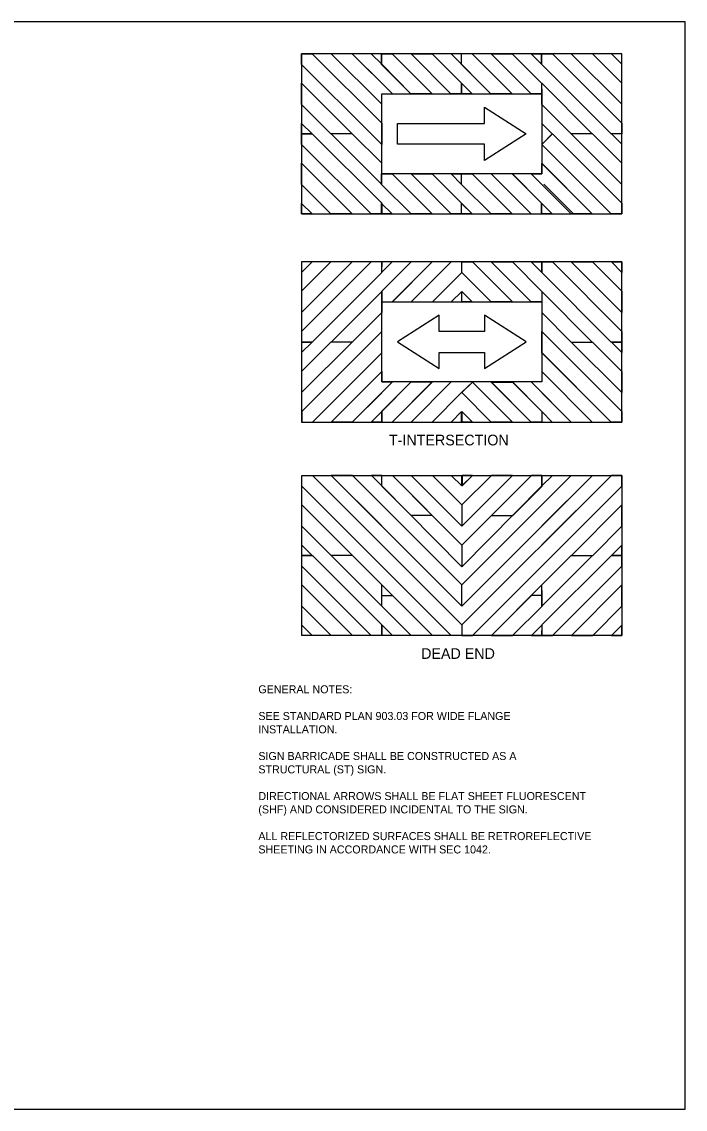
# Model space of a CAD drawing. Extents: x -439.1 to -407.9, y -458.1 to -437.7.
# Drawn here: x -420.29 to -407.86, y -458.05 to -437.68 of the extents above; entities that cross this region are included whole.
import ezdxf

# ---------------------------------------------------------------- set-up
doc = ezdxf.new("R2010")
doc.units = 0
for name, color, linetype in [('Draft_Named_Boundary', 7, 'Continuous'), ('Level 4', 7, 'Continuous'), ('Level 45', 7, 'Continuous')]:
    doc.layers.add(name, color=color, linetype=linetype)

msp = doc.modelspace()

# ---------------------------------------------------------------- linework, layer by layer
at = {"layer": 'Draft_Named_Boundary'}
msp.add_lwpolyline([(-439.109, -458.051), (-407.859, -458.051), (-407.859, -437.676), (-439.109, -437.676)], close=True, dxfattribs=at)
at = {"layer": 'Level 4'}
for p, q in [((-414.849, -438.276), (-413.548, -439.577)), ((-414.496, -438.276), (-413.548, -439.223)), ((-414.098, -438.276), (-413.548, -438.826)), ((-413.744, -438.276), (-413.548, -438.472)), ((-413.352, -438.276), (-412.602, -439.025)), ((-412.998, -438.276), (-412.249, -439.025)), ((-412.6, -438.276), (-412.05, -438.827)), ((-412.247, -438.276), (-412.05, -438.473)), ((-411.852, -438.276), (-411.102, -439.025)), ((-411.498, -438.276), (-410.749, -439.025)), ((-410.747, -438.276), (-410.55, -438.473)), ((-410.349, -438.276), (-409.048, -439.577)), ((-409.996, -438.276), (-409.048, -439.223)), ((-409.598, -438.276), (-409.048, -438.826)), ((-409.244, -438.276), (-409.048, -438.472)), ((-415.048, -438.475), (-413.747, -439.776)), ((-413.55, -438.476), (-413, -439.025)), ((-412.05, -438.476), (-411.5, -439.025)), ((-410.548, -438.475), (-409.247, -439.776)), ((-415.048, -438.828), (-414.101, -439.776)), ((-412.05, -438.829), (-411.854, -439.025)), ((-415.048, -439.226), (-414.498, -439.776)), ((-411.624, -439.275), (-410.843, -439.775)), ((-411.624, -439.58), (-411.624, -439.275)), ((-410.548, -439.226), (-409.998, -439.776)), ((-413.249, -439.971), (-413.249, -439.58)), ((-413.249, -439.58), (-411.624, -439.58)), ((-410.548, -439.58), (-410.352, -439.776)), ((-414.849, -439.776), (-413.548, -441.077)), ((-414.496, -439.776), (-413.548, -440.723)), ((-414.098, -439.776), (-413.548, -440.326)), ((-410.843, -439.775), (-411.624, -440.275)), ((-410.349, -439.776), (-409.048, -441.077)), ((-409.996, -439.776), (-409.048, -440.723)), ((-409.598, -439.776), (-409.048, -440.326)), ((-409.244, -439.776), (-409.048, -439.972)), ((-415.048, -439.975), (-413.747, -441.276)), ((-411.624, -439.971), (-413.249, -439.971)), ((-411.624, -440.275), (-411.624, -439.971)), ((-410.548, -439.975), (-409.247, -441.276)), ((-415.048, -440.328), (-414.101, -441.276)), ((-410.548, -440.328), (-409.601, -441.276)), ((-413.351, -440.525), (-412.6, -441.276)), ((-412.997, -440.525), (-412.247, -441.276)), ((-412.599, -440.525), (-412.05, -441.075)), ((-411.851, -440.525), (-411.1, -441.276)), ((-411.497, -440.525), (-410.747, -441.276)), ((-411.099, -440.525), (-410.55, -441.075)), ((-415.048, -440.726), (-414.498, -441.276)), ((-413.55, -440.724), (-412.998, -441.276)), ((-412.05, -440.724), (-411.498, -441.276)), ((-410.51, -440.721), (-409.961, -441.271)), ((-415.048, -441.08), (-414.852, -441.276)), ((-413.55, -441.078), (-413.352, -441.276)), ((-412.05, -441.078), (-411.852, -441.276)), ((-410.548, -441.08), (-410.352, -441.276)), ((-415.048, -442.372), (-414.852, -442.176)), ((-415.048, -442.726), (-414.498, -442.176)), ((-415.048, -443.123), (-414.101, -442.176)), ((-415.048, -443.477), (-413.747, -442.176)), ((-413.55, -442.374), (-413.352, -442.176)), ((-413.55, -442.727), (-412.998, -442.176)), ((-413.351, -442.926), (-412.6, -442.176)), ((-410.745, -442.926), (-411.496, -442.176)), ((-410.546, -442.727), (-411.098, -442.176)), ((-410.546, -442.374), (-410.744, -442.176)), ((-409.048, -443.477), (-410.349, -442.176)), ((-409.048, -443.123), (-409.996, -442.176)), ((-409.048, -442.726), (-409.598, -442.176)), ((-409.048, -442.372), (-409.244, -442.176)), ((-414.849, -443.676), (-413.548, -442.375)), ((-409.247, -443.676), (-410.548, -442.375)), ((-414.496, -443.676), (-413.548, -442.728)), ((-409.601, -443.676), (-410.548, -442.728)), ((-414.098, -443.676), (-413.548, -443.126)), ((-409.998, -443.676), (-410.548, -443.126)), ((-415.048, -444.226), (-414.498, -443.676)), ((-415.048, -444.623), (-414.101, -443.676)), ((-409.048, -444.977), (-410.349, -443.676)), ((-409.048, -444.623), (-409.996, -443.676)), ((-409.048, -444.226), (-409.598, -443.676)), ((-409.247, -445.176), (-410.548, -443.875)), ((-414.496, -445.176), (-413.548, -444.228)), ((-409.601, -445.176), (-410.548, -444.228)), ((-413.55, -444.976), (-413, -444.426)), ((-413.352, -445.176), (-412.602, -444.426)), ((-412.998, -445.176), (-412.249, -444.426)), ((-411.098, -445.176), (-411.847, -444.426)), ((-410.744, -445.176), (-411.494, -444.426)), ((-410.546, -444.976), (-411.096, -444.426)), ((-414.098, -445.176), (-413.548, -444.626)), ((-412.6, -445.176), (-412.05, -444.625)), ((-411.496, -445.176), (-412.046, -444.625)), ((-409.998, -445.176), (-410.548, -444.626)), ((-413.744, -445.176), (-413.548, -444.98)), ((-412.247, -445.176), (-412.05, -444.979)), ((-411.849, -445.176), (-412.046, -444.979)), ((-410.352, -445.176), (-410.548, -444.98)), ((-414.846, -446.176), (-413.545, -447.477)), ((-414.492, -446.176), (-413.545, -447.123)), ((-414.094, -446.176), (-413.545, -446.726)), ((-413.741, -446.176), (-413.545, -446.372)), ((-413.348, -446.176), (-412.599, -446.925)), ((-412.995, -446.176), (-412.245, -446.925)), ((-412.597, -446.176), (-412.046, -446.727)), ((-412.243, -446.176), (-412.046, -446.373)), ((-411.846, -446.176), (-412.043, -446.373)), ((-411.492, -446.176), (-412.043, -446.727)), ((-411.094, -446.176), (-411.844, -446.925)), ((-410.741, -446.176), (-411.49, -446.925)), ((-410.349, -446.176), (-410.545, -446.372)), ((-409.995, -446.176), (-410.545, -446.726)), ((-409.597, -446.176), (-410.545, -447.123)), ((-409.244, -446.176), (-410.545, -447.477)), ((-415.045, -446.375), (-413.744, -447.676)), ((-413.546, -446.376), (-412.997, -446.925)), ((-410.543, -446.376), (-411.093, -446.925)), ((-409.045, -446.375), (-410.346, -447.676)), ((-415.045, -446.728), (-414.097, -447.676)), ((-409.045, -446.728), (-409.992, -447.676)), ((-415.045, -447.126), (-414.495, -447.676)), ((-409.045, -447.126), (-409.594, -447.676)), ((-414.846, -447.676), (-413.545, -448.977)), ((-414.492, -447.676), (-413.545, -448.623)), ((-414.094, -447.676), (-413.545, -448.226)), ((-409.995, -447.676), (-410.545, -448.226)), ((-409.597, -447.676), (-410.545, -448.623)), ((-409.244, -447.676), (-410.545, -448.977)), ((-415.045, -447.875), (-413.744, -449.176)), ((-409.045, -447.875), (-410.346, -449.176)), ((-415.045, -448.228), (-414.097, -449.176)), ((-409.045, -448.228), (-409.992, -449.176)), ((-413.347, -448.425), (-412.597, -449.176)), ((-410.742, -448.425), (-411.492, -449.176)), ((-415.045, -448.626), (-414.495, -449.176)), ((-413.546, -448.624), (-412.995, -449.176)), ((-410.543, -448.624), (-411.094, -449.176)), ((-409.045, -448.626), (-409.594, -449.176)), ((-415.045, -448.98), (-414.848, -449.176)), ((-413.546, -448.978), (-413.348, -449.176)), ((-410.543, -448.978), (-410.741, -449.176)), ((-409.045, -448.98), (-409.241, -449.176))]:
    msp.add_line(p, q, dxfattribs=at)
for points in [[(-409.048, -438.276), (-415.048, -438.276), (-415.048, -441.276), (-409.048, -441.276)], [(-413.546, -439.579), (-413.546, -439.976), (-413.747, -439.776), (-415.048, -438.475), (-415.048, -438.276), (-414.849, -438.276)], [(-413.548, -439.223), (-413.548, -439.025), (-413.348, -439.025), (-414.098, -438.276), (-414.496, -438.276)], [(-413.548, -438.472), (-413.548, -438.276), (-413.744, -438.276)], [(-412.602, -439.025), (-413, -439.025), (-413.548, -438.472), (-413.548, -438.276), (-413.352, -438.276)], [(-411.854, -439.025), (-412.249, -439.025), (-412.998, -438.276), (-412.6, -438.276)], [(-411.852, -438.276), (-412.247, -438.276), (-411.5, -439.025), (-411.102, -439.025)], [(-411.1, -438.276), (-410.55, -438.827), (-410.549, -439.025), (-410.749, -439.025), (-411.498, -438.276)], [(-410.747, -438.276), (-410.55, -438.276), (-410.55, -438.473)], [(-409.048, -439.577), (-409.048, -439.776), (-409.247, -439.776), (-410.548, -438.475), (-410.548, -438.276), (-410.349, -438.276)], [(-409.048, -439.223), (-409.048, -438.826), (-409.598, -438.276), (-409.996, -438.276)], [(-409.048, -438.472), (-409.048, -438.276), (-409.244, -438.276)], [(-414.101, -439.776), (-414.498, -439.776), (-415.048, -439.226), (-415.048, -438.828)], [(-411.854, -439.025), (-412.05, -439.025), (-412.05, -438.829)], [(-409.601, -439.776), (-409.998, -439.776), (-410.548, -439.226), (-410.548, -438.828)], [(-413.546, -439.025), (-410.546, -439.025), (-410.546, -440.525), (-413.546, -440.525)], [(-414.852, -439.776), (-415.048, -439.776), (-415.048, -439.58)], [(-410.352, -439.776), (-410.546, -439.581), (-410.546, -439.976)], [(-413.548, -441.077), (-413.548, -441.276), (-413.747, -441.276), (-415.048, -439.975), (-415.048, -439.776), (-414.849, -439.776)], [(-413.548, -440.723), (-413.548, -440.326), (-414.098, -439.776), (-414.496, -439.776)], [(-409.048, -441.077), (-409.048, -441.276), (-409.247, -441.276), (-410.548, -439.975), (-410.546, -439.976), (-410.349, -439.776)], [(-409.048, -440.723), (-409.048, -440.326), (-409.598, -439.776), (-409.996, -439.776)], [(-409.048, -439.972), (-409.048, -439.776), (-409.244, -439.776)], [(-414.101, -441.276), (-414.498, -441.276), (-415.048, -440.726), (-415.048, -440.328)], [(-409.601, -441.276), (-409.998, -441.276), (-410.749, -440.525), (-410.546, -440.525), (-410.546, -440.331)], [(-412.6, -441.276), (-412.998, -441.276), (-413.55, -440.724), (-413.55, -440.525), (-413.351, -440.525)], [(-411.852, -441.276), (-412.247, -441.276), (-412.997, -440.525), (-412.599, -440.525)], [(-411.1, -441.276), (-411.498, -441.276), (-412.05, -440.724), (-412.248, -440.525), (-411.85, -440.525)], [(-410.55, -441.075), (-411.1, -440.525), (-411.498, -440.525), (-410.747, -441.276), (-410.55, -441.276)], [(-414.852, -441.276), (-415.048, -441.276), (-415.048, -441.08)], [(-413.55, -441.078), (-413.352, -441.276), (-413.548, -441.276)], [(-410.352, -441.276), (-410.548, -441.276), (-410.548, -441.08)], [(-415.048, -445.176), (-409.048, -445.176), (-409.048, -442.176), (-415.048, -442.176)], [(-413.548, -442.375), (-413.548, -442.176), (-413.747, -442.176), (-415.048, -443.477), (-415.048, -443.676), (-414.849, -443.676)], [(-414.101, -442.176), (-414.498, -442.176), (-415.048, -442.726), (-415.048, -443.123)], [(-414.852, -442.176), (-415.048, -442.176), (-415.048, -442.372)], [(-412.6, -442.176), (-412.998, -442.176), (-413.55, -442.727), (-413.55, -442.926), (-413.348, -442.925)], [(-413.55, -442.374), (-413.352, -442.176), (-413.548, -442.176)], [(-412.598, -442.925), (-412.048, -442.375), (-412.048, -442.176), (-412.247, -442.176), (-412.995, -442.925)], [(-411.495, -442.925), (-412.045, -442.375), (-412.045, -442.176), (-411.846, -442.176), (-411.098, -442.925)], [(-411.496, -442.176), (-411.098, -442.176), (-410.546, -442.727), (-410.546, -442.926), (-410.747, -442.926)], [(-410.546, -442.374), (-410.744, -442.176), (-410.548, -442.176)], [(-410.548, -442.375), (-410.548, -442.176), (-410.349, -442.176), (-409.048, -443.477), (-409.048, -443.676), (-409.247, -443.676)], [(-409.996, -442.176), (-409.598, -442.176), (-409.048, -442.726), (-409.048, -443.123)], [(-409.244, -442.176), (-409.048, -442.176), (-409.048, -442.372)], [(-413.548, -442.728), (-413.548, -443.126), (-414.098, -443.676), (-414.496, -443.676)], [(-412.244, -442.924), (-412.048, -442.924), (-412.048, -442.728)], [(-411.852, -442.924), (-412.048, -442.924), (-412.048, -442.728)], [(-410.548, -442.728), (-410.548, -443.126), (-409.998, -443.676), (-409.601, -443.676)], [(-413.546, -442.925), (-410.546, -442.925), (-410.546, -444.425), (-413.546, -444.425)], [(-413.251, -443.675), (-412.47, -444.175), (-412.47, -443.871), (-411.623, -443.871), (-411.623, -444.175), (-410.842, -443.675), (-411.623, -443.175), (-411.623, -443.48), (-412.47, -443.48), (-412.47, -443.175)], [(-413.546, -443.876), (-413.546, -443.479), (-413.744, -443.676), (-415.045, -444.977), (-415.045, -445.176), (-414.846, -445.176)], [(-410.546, -443.876), (-410.546, -443.479), (-410.349, -443.676), (-409.048, -444.977), (-409.048, -445.176), (-409.247, -445.176)], [(-414.101, -443.676), (-414.498, -443.676), (-415.048, -444.226), (-415.048, -444.623)], [(-414.852, -443.676), (-415.048, -443.676), (-415.048, -443.872)], [(-409.996, -443.676), (-409.598, -443.676), (-409.048, -444.226), (-409.048, -444.623)], [(-409.244, -443.676), (-409.048, -443.676), (-409.048, -443.872)], [(-413.546, -444.227), (-413.546, -444.425), (-413.347, -444.425), (-414.098, -445.176), (-414.496, -445.176)], [(-410.546, -444.23), (-410.546, -444.425), (-410.749, -444.425), (-409.998, -445.176), (-409.601, -445.176)], [(-412.601, -444.425), (-413, -444.426), (-413.548, -444.98), (-413.548, -445.176), (-413.352, -445.176)], [(-412.05, -444.625), (-411.847, -444.426), (-412.248, -444.425), (-412.998, -445.176), (-412.6, -445.176)], [(-412.048, -444.623), (-411.847, -444.426), (-411.098, -445.176), (-411.496, -445.176)], [(-411.495, -444.425), (-411.097, -444.425), (-410.548, -444.98), (-410.548, -445.176), (-410.744, -445.176)], [(-413.548, -444.98), (-413.548, -445.176), (-413.744, -445.176)], [(-412.247, -445.176), (-412.051, -445.176), (-412.051, -444.98)], [(-411.849, -445.176), (-412.045, -445.176), (-412.045, -444.98)], [(-410.548, -444.98), (-410.548, -445.176), (-410.352, -445.176)], [(-415.045, -446.176), (-409.045, -446.176), (-409.045, -449.176), (-415.045, -449.176)], [(-412.045, -448.977), (-412.045, -449.176), (-412.243, -449.176), (-413.744, -447.676), (-415.045, -446.375), (-415.045, -446.176), (-414.846, -446.176)], [(-412.045, -448.623), (-412.045, -448.226), (-414.094, -446.176), (-414.492, -446.176)], [(-413.545, -446.372), (-413.545, -446.176), (-413.741, -446.176)], [(-412.045, -447.48), (-412.045, -447.887), (-413.545, -446.372), (-413.545, -446.176), (-413.348, -446.176)], [(-412.046, -446.727), (-412.045, -447.126), (-412.995, -446.176), (-412.597, -446.176)], [(-412.243, -446.176), (-412.047, -446.176), (-412.047, -446.372)], [(-412.045, -448.623), (-412.045, -448.226), (-409.995, -446.176), (-409.597, -446.176)], [(-412.043, -446.727), (-412.045, -447.126), (-411.094, -446.176), (-411.492, -446.176)], [(-412.045, -447.48), (-412.045, -447.887), (-410.545, -446.372), (-410.545, -446.176), (-410.741, -446.176)], [(-412.045, -448.977), (-412.045, -449.176), (-411.846, -449.176), (-410.346, -447.676), (-409.045, -446.375), (-409.045, -446.176), (-409.244, -446.176)], [(-411.846, -446.176), (-412.042, -446.176), (-412.042, -446.372)], [(-410.545, -446.372), (-410.545, -446.176), (-410.349, -446.176)], [(-414.097, -447.676), (-414.495, -447.676), (-415.045, -447.126), (-415.045, -446.728)], [(-409.992, -447.676), (-409.594, -447.676), (-409.045, -447.126), (-409.045, -446.728)], [(-414.848, -447.676), (-415.045, -447.676), (-415.045, -447.48)], [(-409.241, -447.676), (-409.045, -447.676), (-409.045, -447.48)], [(-413.545, -448.977), (-413.545, -449.176), (-413.744, -449.176), (-415.045, -447.875), (-415.045, -447.676), (-414.846, -447.676)], [(-413.545, -448.623), (-413.545, -448.226), (-414.094, -447.676), (-414.492, -447.676)], [(-410.545, -448.977), (-410.545, -449.176), (-410.346, -449.176), (-409.045, -447.875), (-409.045, -447.676), (-409.244, -447.676)], [(-410.545, -448.623), (-410.545, -448.226), (-409.995, -447.676), (-409.597, -447.676)], [(-414.097, -449.176), (-414.495, -449.176), (-415.045, -448.626), (-415.045, -448.228)], [(-412.597, -449.176), (-412.995, -449.176), (-413.546, -448.624), (-413.546, -448.425), (-413.545, -448.226)], [(-411.492, -449.176), (-411.094, -449.176), (-410.543, -448.624), (-410.543, -448.425), (-410.545, -448.226)], [(-409.992, -449.176), (-409.594, -449.176), (-409.045, -448.626), (-409.045, -448.228)], [(-414.848, -449.176), (-415.045, -449.176), (-415.045, -448.98)], [(-413.546, -448.978), (-413.348, -449.176), (-413.545, -449.176)], [(-410.543, -448.978), (-410.741, -449.176), (-410.545, -449.176)], [(-409.241, -449.176), (-409.045, -449.176), (-409.045, -448.98)]]:
    msp.add_lwpolyline(points, close=True, dxfattribs=at)
for points in [[(-413.352, -438.276), (-412.602, -439.025), (-413, -439.025), (-413.55, -438.476), (-413.55, -438.276)], [(-412.6, -438.276), (-412.05, -438.827), (-412.05, -439.025), (-412.249, -439.025), (-412.998, -438.276)], [(-412.247, -438.276), (-412.05, -438.473), (-412.05, -438.276)], [(-411.852, -438.276), (-411.102, -439.025), (-411.5, -439.025), (-412.05, -438.476), (-412.05, -438.276)], [(-411.1, -438.276), (-410.55, -438.827), (-410.55, -439.025), (-410.749, -439.025), (-411.498, -438.276)], [(-410.747, -438.276), (-410.55, -438.473), (-410.55, -438.276)], [(-412.998, -441.276), (-413.55, -440.724), (-413.55, -440.525), (-413.351, -440.525), (-412.6, -441.276)], [(-412.05, -441.276), (-412.05, -441.075), (-412.599, -440.525), (-412.997, -440.525), (-412.247, -441.276)], [(-411.498, -441.276), (-412.05, -440.724), (-412.05, -440.525), (-411.851, -440.525), (-411.1, -441.276)], [(-410.55, -441.276), (-410.55, -441.075), (-411.099, -440.525), (-411.497, -440.525), (-410.747, -441.276)], [(-413.55, -441.276), (-413.55, -441.078), (-413.352, -441.276)], [(-412.998, -442.176), (-413.55, -442.727), (-413.55, -442.926), (-413.351, -442.926), (-412.6, -442.176)], [(-413.55, -442.176), (-413.55, -442.374), (-413.352, -442.176)], [(-411.098, -442.176), (-410.546, -442.727), (-410.546, -442.926), (-410.745, -442.926), (-411.496, -442.176)], [(-410.546, -442.176), (-410.546, -442.374), (-410.744, -442.176)], [(-413.352, -445.176), (-412.602, -444.426), (-413, -444.426), (-413.55, -444.976), (-413.55, -445.176)], [(-410.744, -445.176), (-411.494, -444.426), (-411.096, -444.426), (-410.546, -444.976), (-410.546, -445.176)], [(-412.247, -445.176), (-412.05, -444.979), (-412.05, -445.176)], [(-411.849, -445.176), (-412.046, -444.979), (-412.046, -445.176)], [(-413.348, -446.176), (-412.599, -446.925), (-412.997, -446.925), (-413.546, -446.376), (-413.546, -446.176)], [(-412.243, -446.176), (-412.046, -446.373), (-412.046, -446.176)], [(-411.846, -446.176), (-412.043, -446.373), (-412.043, -446.176)], [(-410.741, -446.176), (-411.49, -446.925), (-411.093, -446.925), (-410.543, -446.376), (-410.543, -446.176)], [(-412.995, -449.176), (-413.546, -448.624), (-413.546, -448.425), (-413.347, -448.425), (-412.597, -449.176)], [(-411.094, -449.176), (-410.543, -448.624), (-410.543, -448.425), (-410.742, -448.425), (-411.492, -449.176)], [(-413.546, -449.176), (-413.546, -448.978), (-413.348, -449.176)], [(-410.543, -449.176), (-410.543, -448.978), (-410.741, -449.176)]]:
    msp.add_lwpolyline(points, dxfattribs=at)

# ---------------------------------------------------------------- texts
for s, p in [('T-INTERSECTION', (-413.411, -445.613)), ('DEAD END', (-412.808, -449.613))]:
    msp.add_text(s, height=0.2, dxfattribs=at).set_placement(p)
at = {"layer": 'Level 45'}
for s, p in [('GENERAL NOTES: ', (-415.859, -450.258)), ('SEE STANDARD PLAN 903.03 FOR WIDE FLANGE', (-415.859, -450.758)), ('INSTALLATION.', (-415.859, -451.008)), ('SIGN BARRICADE SHALL BE CONSTRUCTED AS A', (-415.859, -451.508)), ('STRUCTURAL (ST) SIGN.', (-415.859, -451.758)), ('DIRECTIONAL ARROWS SHALL BE FLAT SHEET FLUORESCENT', (-415.859, -452.258)), ('(SHF) AND CONSIDERED INCIDENTAL TO THE SIGN.', (-415.859, -452.508)), ('ALL REFLECTORIZED SURFACES SHALL BE RETROREFLECTIVE ', (-415.859, -453.008)), ('SHEETING IN ACCORDANCE WITH SEC 1042.', (-415.859, -453.258))]:
    msp.add_text(s, height=0.15, dxfattribs=at).set_placement(p)

doc.saveas('drawing.dxf')
